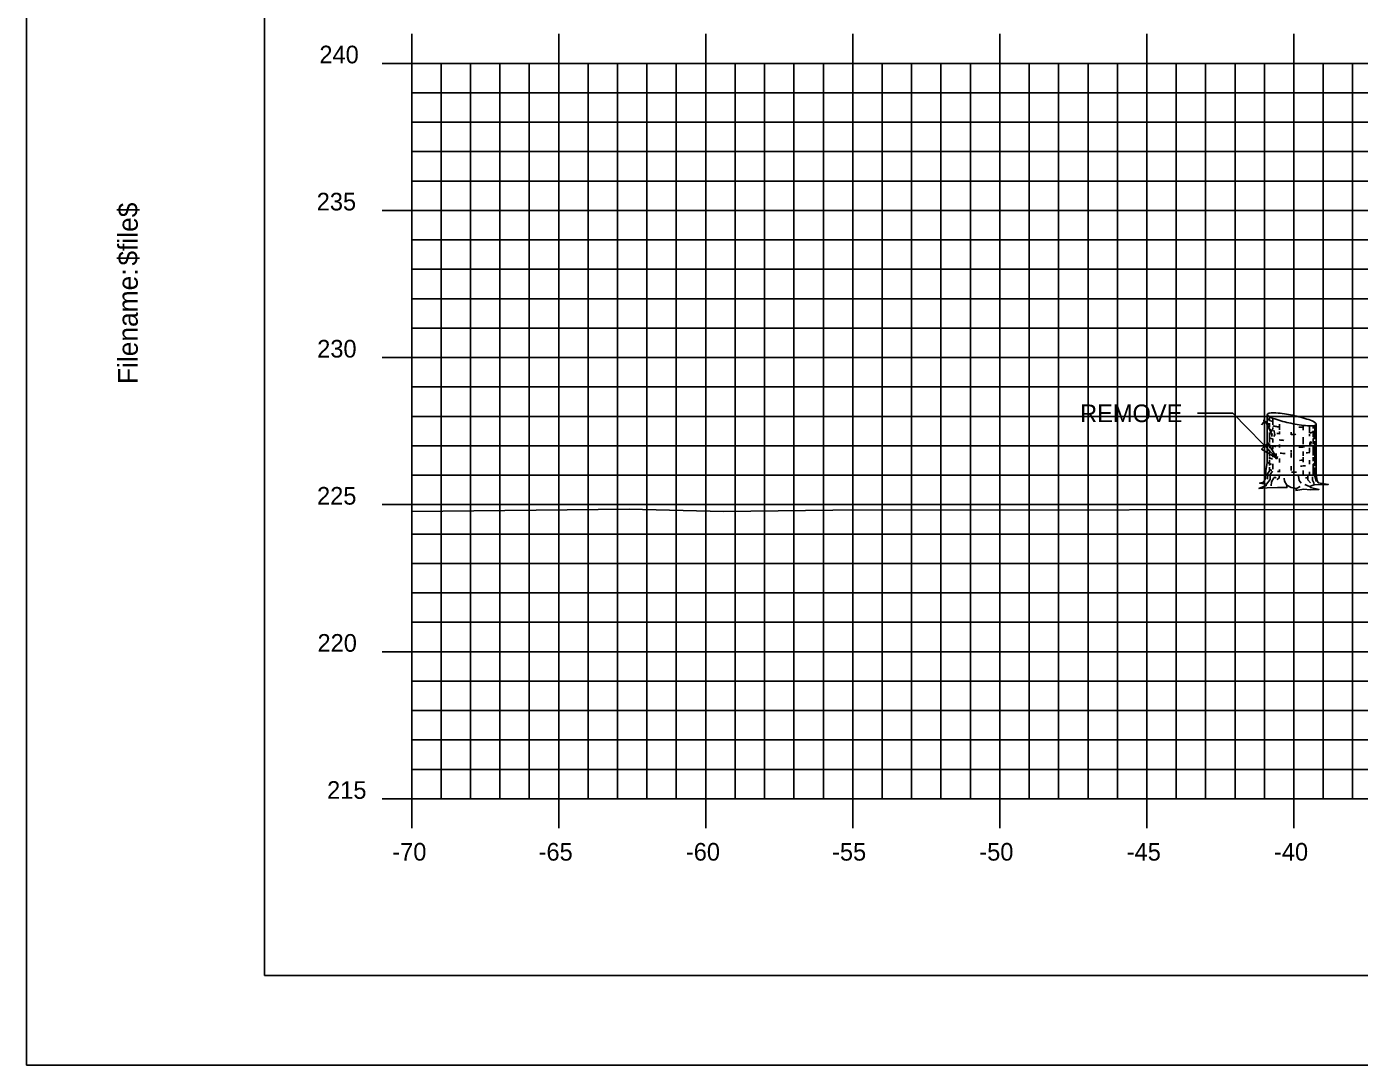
# Model space of a CAD drawing. Extents: x 1136989 to 1137159, y 608981 to 609091.
# Drawn here: x 1136989.05 to 1137034.37, y 608981.28 to 609016.58 of the extents above; entities that cross this region are included whole.
import ezdxf

# ---------------------------------------------------------------- set-up
doc = ezdxf.new("R2010")
doc.units = 0
for name, color, linetype in [('ANNOTATION', 7, 'Continuous'), ('BORDER', 7, 'Continuous'), ('H_V ANNOTATION', 7, 'Continuous'), ('MAJOR', 7, 'Continuous'), ('MINOR', 7, 'Continuous'), ('PLOT BOUNDARY', 7, 'Continuous'), ('S_Roadway_Centerline', 7, 'Continuous'), ('S_Trees_Conifer_Pay', 7, 'Continuous')]:
    doc.layers.add(name, color=color, linetype=linetype)

msp = doc.modelspace()

# ---------------------------------------------------------------- linework, layer by layer
at = {"layer": 'ANNOTATION'}
for p in [(1137028.862, 609003.439), (1137031.572, 609001.898)]:
    msp.add_line(p, (1137030.062, 609003.439), dxfattribs=at)
msp.add_lwpolyline([(1137031.259, 609002.431), (1137031.572, 609001.898), (1137031.045, 609002.222)], close=True, dxfattribs=at)
at = {"layer": 'BORDER'}
msp.add_lwpolyline([(1136997.14, 608984.335), (1137157.14, 608984.335), (1137157.14, 609089.335), (1136997.14, 609089.335)], close=True, dxfattribs=at)
at = {"layer": 'MAJOR'}
for p, q in [((1137002.14, 609016.337), (1137002.14, 609015.335)), ((1137007.14, 609016.337), (1137007.14, 609015.335)), ((1137012.14, 609016.337), (1137012.14, 609015.335)), ((1137017.14, 609016.337), (1137017.14, 609015.335)), ((1137022.14, 609016.337), (1137022.14, 609015.335)), ((1137027.14, 609016.337), (1137027.14, 609015.335)), ((1137032.14, 609016.337), (1137032.14, 609015.335)), ((1137001.138, 609015.335), (1137002.14, 609015.335)), ((1137002.14, 609015.335), (1137142.14, 609015.335)), ((1137002.14, 608990.335), (1137002.14, 609015.335)), ((1137002.14, 608990.335), (1137002.14, 609015.335)), ((1137002.14, 609015.335), (1137142.14, 609015.335)), ((1137007.14, 608990.335), (1137007.14, 609015.335)), ((1137012.14, 608990.335), (1137012.14, 609015.335)), ((1137017.14, 608990.335), (1137017.14, 609015.335)), ((1137022.14, 608990.335), (1137022.14, 609015.335)), ((1137027.14, 608990.335), (1137027.14, 609015.335)), ((1137032.14, 608990.335), (1137032.14, 609015.335)), ((1137001.138, 609010.335), (1137002.14, 609010.335)), ((1137002.14, 609010.335), (1137142.14, 609010.335)), ((1137001.138, 609005.335), (1137002.14, 609005.335)), ((1137002.14, 609005.335), (1137142.14, 609005.335)), ((1137001.138, 609000.335), (1137002.14, 609000.335)), ((1137002.14, 609000.335), (1137142.14, 609000.335)), ((1137001.138, 608995.335), (1137002.14, 608995.335)), ((1137002.14, 608995.335), (1137142.14, 608995.335)), ((1137001.138, 608990.335), (1137002.14, 608990.335)), ((1137002.14, 608990.335), (1137142.14, 608990.335)), ((1137002.14, 608990.335), (1137142.14, 608990.335)), ((1137002.14, 608989.333), (1137002.14, 608990.335)), ((1137007.14, 608989.333), (1137007.14, 608990.335)), ((1137012.14, 608989.333), (1137012.14, 608990.335)), ((1137017.14, 608989.333), (1137017.14, 608990.335)), ((1137022.14, 608989.333), (1137022.14, 608990.335)), ((1137027.14, 608989.333), (1137027.14, 608990.335)), ((1137032.14, 608989.333), (1137032.14, 608990.335))]:
    msp.add_line(p, q, dxfattribs=at)
at = {"layer": 'MINOR'}
for p, q in [((1137003.14, 608990.335), (1137003.14, 609015.335)), ((1137004.14, 608990.335), (1137004.14, 609015.335)), ((1137005.14, 608990.335), (1137005.14, 609015.335)), ((1137006.14, 608990.335), (1137006.14, 609015.335)), ((1137008.14, 608990.335), (1137008.14, 609015.335)), ((1137009.14, 608990.335), (1137009.14, 609015.335)), ((1137010.14, 608990.335), (1137010.14, 609015.335)), ((1137011.14, 608990.335), (1137011.14, 609015.335)), ((1137013.14, 608990.335), (1137013.14, 609015.335)), ((1137014.14, 608990.335), (1137014.14, 609015.335)), ((1137015.14, 608990.335), (1137015.14, 609015.335)), ((1137016.14, 608990.335), (1137016.14, 609015.335)), ((1137018.14, 608990.335), (1137018.14, 609015.335)), ((1137019.14, 608990.335), (1137019.14, 609015.335)), ((1137020.14, 608990.335), (1137020.14, 609015.335)), ((1137021.14, 608990.335), (1137021.14, 609015.335)), ((1137023.14, 608990.335), (1137023.14, 609015.335)), ((1137024.14, 608990.335), (1137024.14, 609015.335)), ((1137025.14, 608990.335), (1137025.14, 609015.335)), ((1137026.14, 608990.335), (1137026.14, 609015.335)), ((1137028.14, 608990.335), (1137028.14, 609015.335)), ((1137029.14, 608990.335), (1137029.14, 609015.335)), ((1137030.14, 608990.335), (1137030.14, 609015.335)), ((1137031.14, 608990.335), (1137031.14, 609015.335)), ((1137033.14, 608990.335), (1137033.14, 609015.335)), ((1137034.14, 608990.335), (1137034.14, 609015.335)), ((1137002.14, 609014.335), (1137142.14, 609014.335)), ((1137002.14, 609014.335), (1137003.142, 609014.335)), ((1137002.14, 609013.335), (1137142.14, 609013.335)), ((1137002.14, 609013.335), (1137003.142, 609013.335)), ((1137002.14, 609012.335), (1137142.14, 609012.335)), ((1137002.14, 609012.335), (1137003.142, 609012.335)), ((1137002.14, 609011.335), (1137142.14, 609011.335)), ((1137002.14, 609011.335), (1137003.142, 609011.335)), ((1137002.14, 609009.335), (1137142.14, 609009.335)), ((1137002.14, 609009.335), (1137003.142, 609009.335)), ((1137002.14, 609008.335), (1137142.14, 609008.335)), ((1137002.14, 609008.335), (1137003.142, 609008.335)), ((1137002.14, 609007.335), (1137142.14, 609007.335)), ((1137002.14, 609007.335), (1137003.142, 609007.335)), ((1137002.14, 609006.335), (1137142.14, 609006.335)), ((1137002.14, 609006.335), (1137003.142, 609006.335)), ((1137002.14, 609004.335), (1137142.14, 609004.335)), ((1137002.14, 609004.335), (1137003.142, 609004.335)), ((1137002.14, 609003.335), (1137142.14, 609003.335)), ((1137002.14, 609003.335), (1137003.142, 609003.335)), ((1137002.14, 609002.335), (1137142.14, 609002.335)), ((1137002.14, 609002.335), (1137003.142, 609002.335)), ((1137002.14, 609001.335), (1137142.14, 609001.335)), ((1137002.14, 609001.335), (1137003.142, 609001.335)), ((1137002.14, 608999.335), (1137142.14, 608999.335)), ((1137002.14, 608999.335), (1137003.142, 608999.335)), ((1137002.14, 608998.335), (1137142.14, 608998.335)), ((1137002.14, 608998.335), (1137003.142, 608998.335)), ((1137002.14, 608997.335), (1137142.14, 608997.335)), ((1137002.14, 608997.335), (1137003.142, 608997.335)), ((1137002.14, 608996.335), (1137142.14, 608996.335)), ((1137002.14, 608996.335), (1137003.142, 608996.335)), ((1137002.14, 608994.335), (1137142.14, 608994.335)), ((1137002.14, 608994.335), (1137003.142, 608994.335)), ((1137002.14, 608993.335), (1137142.14, 608993.335)), ((1137002.14, 608993.335), (1137003.142, 608993.335)), ((1137002.14, 608992.335), (1137142.14, 608992.335)), ((1137002.14, 608992.335), (1137003.142, 608992.335)), ((1137002.14, 608991.335), (1137142.14, 608991.335)), ((1137002.14, 608991.335), (1137003.142, 608991.335))]:
    msp.add_line(p, q, dxfattribs=at)
at = {"layer": 'PLOT BOUNDARY'}
msp.add_lwpolyline([(1136989.047, 608981.276), (1137159.047, 608981.276), (1137159.047, 609091.276), (1136989.047, 609091.276)], close=True, dxfattribs=at)
at = {"layer": 'S_Roadway_Centerline'}
msp.add_lwpolyline([(1137002.14, 609000.098), (1137009.532, 609000.178), (1137012.739, 609000.098), (1137016.466, 609000.152), (1137036.626, 609000.169), (1137038.714, 609000.163), (1137041.2, 609000.115), (1137042.648, 609000.935), (1137061.665, 609005.086), (1137063.035, 609005.338), (1137063.585, 609005.359), (1137073.925, 609005.86), (1137075.247, 609005.88), (1137084.732, 609006.033), (1137090.016, 609005.053), (1137090.597, 609004.926), (1137092.675, 609004.125), (1137094.237, 609003.522), (1137106.232, 609002.947), (1137113.452, 609002.818), (1137121.89, 609002.73), (1137136.879, 609002.44), (1137141.584, 609002.392), (1137142.14, 609002.4)], dxfattribs=at)
at = {"layer": 'S_Trees_Conifer_Pay'}
for p, q in [((1137031.238, 609001.756), (1137031.238, 609003.403)), ((1137031.31, 609003.331), (1137031.31, 609003.168)), ((1137031.31, 609003.101), (1137031.31, 609002.973)), ((1137031.427, 609003.27), (1137031.427, 609003.047)), ((1137031.427, 609002.958), (1137031.427, 609002.911)), ((1137031.656, 609003.074), (1137031.656, 609002.874)), ((1137032.452, 609003.032), (1137032.452, 609002.864)), ((1137032.672, 609003.011), (1137032.672, 609002.779)), ((1137032.797, 609003.019), (1137032.797, 609002.921)), ((1137032.855, 609003.03), (1137032.855, 609002.559)), ((1137032.902, 609001.346), (1137032.902, 609003.068)), ((1137031.31, 609002.786), (1137031.31, 609002.45)), ((1137031.37, 609002.775), (1137031.422, 609002.715)), ((1137031.427, 609002.576), (1137031.427, 609002.444)), ((1137031.656, 609002.816), (1137031.656, 609002.728)), ((1137032.046, 609002.8), (1137032.046, 609002.705)), ((1137032.452, 609002.627), (1137032.452, 609002.39)), ((1137032.672, 609002.738), (1137032.672, 609002.664)), ((1137032.797, 609002.847), (1137032.797, 609002.643)), ((1137032.797, 609002.585), (1137032.797, 609002.386)), ((1137032.855, 609002.495), (1137032.855, 609002.187)), ((1137031.31, 609002.413), (1137031.31, 609002.25)), ((1137031.31, 609002.203), (1137031.31, 609001.986)), ((1137031.427, 609002.333), (1137031.427, 609002.223)), ((1137031.427, 609002.087), (1137031.427, 609001.946)), ((1137031.656, 609002.38), (1137031.656, 609002.275)), ((1137032.046, 609002.187), (1137032.046, 609002.112)), ((1137032.046, 609002.087), (1137032.046, 609001.939)), ((1137032.452, 609002.145), (1137032.452, 609001.993)), ((1137032.672, 609002.261), (1137032.672, 609002.122)), ((1137032.797, 609002.339), (1137032.797, 609002.003)), ((1137032.855, 609002.139), (1137032.855, 609001.647)), ((1137031.31, 609001.956), (1137031.31, 609001.881)), ((1137031.31, 609001.841), (1137031.31, 609001.668)), ((1137031.427, 609001.719), (1137031.427, 609001.546)), ((1137031.656, 609001.908), (1137031.656, 609001.762)), ((1137032.046, 609001.647), (1137032.046, 609001.494)), ((1137032.452, 609001.95), (1137032.452, 609001.776)), ((1137032.672, 609001.851), (1137032.672, 609001.709)), ((1137032.797, 609001.95), (1137032.797, 609001.814)), ((1137032.797, 609001.715), (1137032.797, 609001.336)), ((1137032.855, 609001.593), (1137032.855, 609001.346)), ((1137031.656, 609001.53), (1137031.656, 609001.441)), ((1137032.452, 609001.499), (1137032.452, 609001.346)), ((1137032.672, 609001.447), (1137032.672, 609001.353)), ((1137032.234, 609000.889), (1137032.36, 609000.953)), ((1137032.672, 609000.953), (1137032.509, 609001.017))]:
    msp.add_line(p, q, dxfattribs=at)
for points in [[(1137031.193, 609003.134), (1137031.117, 609003.142), (1137031.045, 609003.043)], [(1137031.422, 609002.901), (1137031.385, 609002.827), (1137031.338, 609002.884), (1137031.28, 609002.952), (1137031.187, 609003.146), (1137031.123, 609003.193), (1137031.092, 609003.2)], [(1137031.407, 609002.648), (1137031.37, 609002.775), (1137031.307, 609002.891), (1137031.276, 609002.958), (1137031.207, 609003.105)], [(1137031.455, 609002.864), (1137031.486, 609002.779), (1137031.49, 609002.711), (1137031.459, 609002.648)], [(1137032.723, 609002.374), (1137032.729, 609002.469), (1137032.686, 609002.446), (1137032.686, 609002.351)], [(1137031.584, 609001.975), (1137031.572, 609001.898), (1137031.525, 609001.908), (1137031.537, 609002.075)], [(1137031.238, 609001.756), (1137031.187, 609001.494), (1137031.171, 609001.221), (1137031.113, 609001.095), (1137030.977, 609001.065), (1137031.208, 609001.027), (1137031.208, 609001.027), (1137031.202, 609000.98), (1137030.954, 609000.885), (1137031.229, 609000.902), (1137031.584, 609000.922), (1137031.906, 609000.912), (1137031.899, 609000.994), (1137032.047, 609000.912), (1137032.234, 609000.889), (1137032.21, 609000.821), (1137032.478, 609000.864), (1137032.698, 609000.837), (1137032.991, 609000.855), (1137032.702, 609000.912), (1137032.672, 609000.953), (1137032.834, 609001.011), (1137033.071, 609001.021), (1137033.312, 609001.021), (1137032.97, 609001.079), (1137032.929, 609001.159), (1137032.902, 609001.346)], [(1137031.313, 609001.614), (1137031.307, 609001.468), (1137031.259, 609001.4), (1137031.249, 609001.2)], [(1137031.412, 609001.468), (1137031.338, 609001.363), (1137031.333, 609001.19), (1137031.208, 609001.027)], [(1137031.37, 609000.974), (1137031.385, 609001.112), (1137031.459, 609001.241)], [(1137031.649, 609001.363), (1137031.638, 609001.237), (1137031.564, 609001.194)], [(1137031.899, 609000.994), (1137031.825, 609001.136), (1137031.815, 609001.237)], [(1137032.387, 609001.065), (1137032.32, 609001.159), (1137032.293, 609001.299)], [(1137032.614, 609001.305), (1137032.614, 609001.173), (1137032.702, 609001.074)], [(1137032.776, 609001.278), (1137032.771, 609001.163), (1137032.824, 609001.074), (1137032.834, 609001.011)], [(1137032.855, 609001.299), (1137032.876, 609001.221), (1137032.896, 609001.126)]]:
    msp.add_lwpolyline(points, dxfattribs=at)
for centre, radius, start, end in [((1137031.261, 609003.403), 0.0226, 168.2806, 179.9685), ((1137031.265, 609003.403), 0.0264, 179.9685, 190.7806), ((1137031.261, 609003.403), 0.0226, 156.5926, 168.2806), ((1137031.27, 609003.404), 0.0314, 190.7806, 203.4842), ((1137031.264, 609003.402), 0.0264, 145.7806, 156.5926), ((1137031.289, 609003.413), 0.0527, 203.4842, 213.2806), ((1137031.269, 609003.399), 0.0314, 133.077, 145.7806), ((1137031.313, 609003.429), 0.0817, 213.2806, 227.6113), ((1137031.283, 609003.383), 0.0527, 123.2806, 133.077), ((1137031.299, 609003.359), 0.0817, 108.9499, 123.2806), ((1137031.427, 609003.553), 0.251, 227.6113, 235.7806), ((1137031.354, 609003.199), 0.251, 100.7806, 108.9499), ((1137031.457, 609002.658), 0.802, 84.6206, 100.7806), ((1137031.047, 608998.3), 5.179, 78.2806, 84.6206), ((1137031.047, 608998.3), 5.179, 71.9406, 78.2806), ((1137031.272, 609003.277), 0.0334, 185.7849, 196.0515), ((1137031.272, 609003.122), 0.0334, 185.7849, 196.0515), ((1137031.282, 609003.28), 0.0441, 196.0515, 210), ((1137031.282, 609003.125), 0.0441, 196.0515, 210), ((1137031.298, 609003.289), 0.0624, 210, 228.7494), ((1137031.298, 609003.135), 0.0624, 210, 228.7494), ((1137031.37, 609003.372), 0.172, 228.7494, 240), ((1137031.37, 609003.217), 0.172, 228.7494, 240), ((1137031.569, 609003.562), 0.571, 240, 242.9763), ((1137031.737, 609004.009), 0.802, 235.7806, 251.9406), ((1137031.569, 609003.717), 0.571, 247.5868, 255.5683), ((1137031.569, 609003.562), 0.571, 255.6333, 261.8968), ((1137033.094, 609008.171), 5.179, 251.9406, 258.2806), ((1137032.07, 609007.08), 4.124, 261.8968, 263.762), ((1137033.094, 609008.171), 5.179, 258.2806, 264.6206), ((1137032.07, 609007.08), 4.124, 273.2669, 275.3045), ((1137032.684, 609003.813), 0.802, 264.6206, 280.7806), ((1137032.404, 609002.462), 0.802, 55.7806, 71.9406), ((1137032.787, 609003.271), 0.251, 280.7806, 288.9499), ((1137032.713, 609002.917), 0.251, 47.6113, 55.7806), ((1137032.842, 609003.112), 0.0817, 288.9499, 303.2806), ((1137032.827, 609003.042), 0.0817, 33.2806, 47.6113), ((1137032.858, 609003.087), 0.0527, 303.2806, 313.077), ((1137032.872, 609003.072), 0.0314, 313.077, 325.7806), ((1137032.851, 609003.058), 0.0527, 23.4842, 33.2806), ((1137032.876, 609003.069), 0.0264, 325.7806, 336.5926), ((1137032.871, 609003.067), 0.0314, 10.7806, 23.4842), ((1137032.88, 609003.067), 0.0226, 336.5926, 348.2806), ((1137032.876, 609003.067), 0.0264, 359.9685, 10.7806), ((1137032.88, 609003.067), 0.0226, 348.2806, 359.9685), ((1137031.272, 609002.678), 0.0334, 185.7849, 196.0515), ((1137031.57, 609003.118), 0.571, 242.9571, 255.5507), ((1137032.072, 609006.847), 4.124, 262.9442, 264.2151), ((1137032.07, 609006.636), 4.124, 264.0496, 266.2948), ((1137032.072, 609006.847), 4.124, 269.6419, 270), ((1137032.072, 609006.847), 4.124, 270, 271.9249), ((1137032.572, 609003.329), 0.571, 282.0154, 293.1403), ((1137032.571, 609003.118), 0.571, 292.9413, 300), ((1137032.572, 609003.329), 0.571, 299.6633, 300), ((1137032.772, 609002.984), 0.172, 300, 311.2506), ((1137032.844, 609002.902), 0.0624, 311.2506, 330), ((1137032.86, 609002.892), 0.0441, 330, 343.9485), ((1137032.87, 609002.89), 0.0334, 0, 16.0515), ((1137032.87, 609002.89), 0.0334, 343.9485, 360), ((1137032.87, 609002.443), 0.0334, 0, 16.0515), ((1137031.273, 609002.443), 0.0334, 185.7849, 196.0515), ((1137031.273, 609002.233), 0.0334, 185.7849, 196.0515), ((1137031.283, 609002.446), 0.0441, 196.0515, 210), ((1137031.283, 609002.236), 0.0441, 196.0515, 210), ((1137031.299, 609002.455), 0.0624, 210, 228.7494), ((1137031.299, 609002.245), 0.0624, 210, 228.7494), ((1137031.372, 609002.537), 0.172, 228.7494, 240), ((1137031.372, 609002.327), 0.172, 228.7494, 240), ((1137031.571, 609002.882), 0.571, 240, 242.8104), ((1137031.571, 609002.672), 0.571, 240, 242.8104), ((1137031.571, 609002.882), 0.571, 253.0704, 261.8968), ((1137032.072, 609006.4), 4.124, 261.8968, 262.3875), ((1137032.072, 609006.19), 4.124, 264.5431, 266.8507), ((1137032.072, 609006.19), 4.124, 269.6419, 270), ((1137032.072, 609006.4), 4.124, 273.3324, 275.919), ((1137032.072, 609006.19), 4.124, 276.8526, 278.1032), ((1137032.572, 609002.672), 0.571, 278.1032, 280.7293), ((1137032.572, 609002.672), 0.571, 293.1403, 300), ((1137032.572, 609002.882), 0.571, 299.6633, 300), ((1137032.772, 609002.537), 0.172, 300, 311.2506), ((1137032.772, 609002.327), 0.172, 300, 311.2506), ((1137032.844, 609002.455), 0.0624, 311.2506, 330), ((1137032.844, 609002.245), 0.0624, 311.2506, 330), ((1137032.86, 609002.446), 0.0441, 330, 343.9485), ((1137032.86, 609002.236), 0.0441, 330, 343.9485), ((1137032.87, 609002.443), 0.0334, 343.9485, 360), ((1137032.87, 609002.233), 0.0334, 0, 16.0515), ((1137032.87, 609002.233), 0.0334, 343.9485, 360), ((1137032.87, 609001.996), 0.0334, 0, 16.0515), ((1137031.273, 609001.798), 0.0334, 185.7849, 196.0515), ((1137031.283, 609001.801), 0.0441, 196.0515, 210), ((1137031.299, 609001.81), 0.0624, 210, 228.7494), ((1137031.372, 609001.893), 0.172, 228.7494, 240), ((1137031.571, 609002.238), 0.571, 240, 250.7093), ((1137031.571, 609002.436), 0.571, 242.8104, 254.6017), ((1137032.072, 609005.953), 4.124, 273.6807, 275.284), ((1137032.072, 609005.756), 4.124, 274.1603, 276.5009), ((1137032.572, 609002.436), 0.571, 293.1403, 300), ((1137032.583, 609002.244), 0.571, 291.9732, 298.7631), ((1137032.572, 609002.042), 0.571, 293.1403, 300), ((1137032.772, 609002.091), 0.172, 300, 311.2506), ((1137032.772, 609001.697), 0.172, 300, 311.2506), ((1137032.844, 609002.008), 0.0624, 311.2506, 330), ((1137032.844, 609001.615), 0.0624, 311.2506, 330), ((1137032.86, 609001.999), 0.0441, 330, 343.9485), ((1137032.86, 609001.606), 0.0441, 330, 343.9485), ((1137032.87, 609001.996), 0.0334, 343.9485, 360), ((1137032.87, 609001.798), 0.0334, 0, 16.0515), ((1137032.87, 609001.603), 0.0334, 0, 16.0515), ((1137032.87, 609001.603), 0.0334, 343.9485, 360), ((1137031.273, 609001.382), 0.0334, 185.7849, 196.0515), ((1137031.283, 609001.385), 0.0441, 196.0515, 210), ((1137031.299, 609001.394), 0.0624, 210, 228.7494), ((1137031.372, 609001.477), 0.172, 228.7494, 240), ((1137031.571, 609002.042), 0.571, 242.7279, 251.4933), ((1137031.571, 609001.822), 0.571, 258.363, 261.8968), ((1137032.072, 609005.34), 4.124, 261.8968, 262.6316), ((1137032.072, 609005.56), 4.124, 263.2104, 264.2151), ((1137032.072, 609005.56), 4.124, 269.8672, 270), ((1137032.072, 609005.56), 4.124, 270, 272.1883), ((1137032.072, 609005.34), 4.124, 276.488, 277.5562), ((1137032.572, 609001.822), 0.571, 295.4686, 300), ((1137032.772, 609001.477), 0.172, 300, 311.2506), ((1137032.844, 609001.394), 0.0624, 311.2506, 330), ((1137032.86, 609001.385), 0.0441, 330, 343.9485), ((1137032.87, 609001.382), 0.0334, 0, 16.0515), ((1137032.87, 609001.382), 0.0334, 343.9485, 360)]:
    msp.add_arc(centre, radius, start, end, dxfattribs=at)

# ---------------------------------------------------------------- texts
at = {"layer": 'ANNOTATION'}
msp.add_text('REMOVE', height=0.6, dxfattribs=at).set_placement((1137024.871, 609003.139))
at = {"layer": 'BORDER'}
for s, p in [('$file$', (1136992.825, 609008.461)), ('Filename:', (1136992.825, 609004.433))]:
    msp.add_text(s, height=0.6696, rotation=90, dxfattribs=at).set_placement(p)
at = {"layer": 'H_V ANNOTATION'}
for s, p in [('240', (1136999.002, 609015.335)), ('235', (1136998.911, 609010.335)), ('230', (1136998.927, 609005.335)), ('225', (1136998.922, 609000.335)), ('220', (1136998.938, 608995.335)), ('215', (1136999.264, 608990.335)), ('-70', (1137001.481, 608988.235)), ('-65', (1137006.457, 608988.235)), ('-60', (1137011.465, 608988.235)), ('-55', (1137016.436, 608988.235)), ('-50', (1137021.444, 608988.235)), ('-45', (1137026.457, 608988.235)), ('-40', (1137031.465, 608988.235))]:
    msp.add_text(s, height=0.6, dxfattribs=at).set_placement(p)
at = {"layer": 'MAJOR'}
msp.add_text('-', height=0.006, dxfattribs=at).set_placement((1137002.135, 608990.335))

doc.saveas('drawing.dxf')
